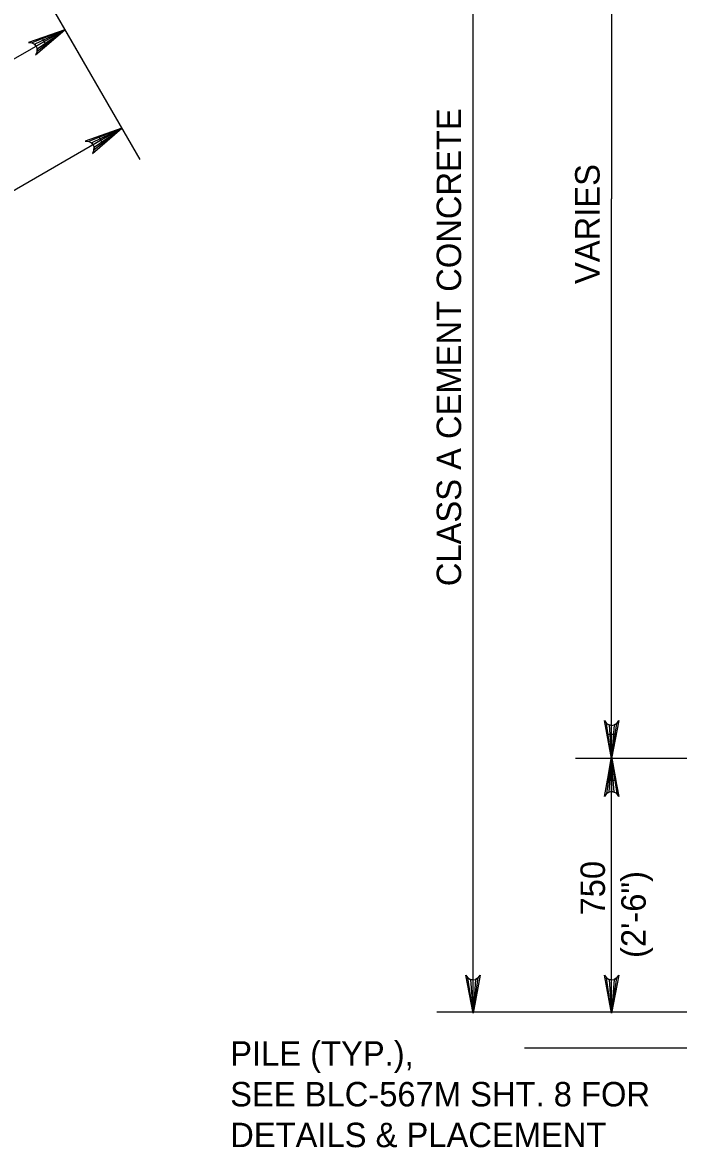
# Model space of a CAD drawing. Extents: x 638340 to 640241, y 295465 to 298435.
# Drawn here: x 638939.7 to 639020.2, y 296989.3 to 297127.3 of the extents above; entities that cross this region are included whole.
import ezdxf

# ---------------------------------------------------------------- set-up
doc = ezdxf.new("R2010")
doc.units = 0
doc.layers.add('3', color=7, linetype='Continuous')

msp = doc.modelspace()

# ---------------------------------------------------------------- linework, layer by layer
at = {"layer": '3'}
for p, q in [((638994.99, 297005.79), (638994.99, 297174.31)), ((639011.99, 297174.31), (639011.99, 297105.67)), ((638919.46, 297170.52), (638947.13, 297122.59)), ((638941.59, 297132.18), (638954.12, 297110.49)), ((638944.92, 297126.42), (638870.33, 297083.36)), ((638951.91, 297114.32), (638874.95, 297069.9)), ((639011.99, 297037.02), (639011.99, 297105.67)), ((639063.19, 297037.02), (639007.56, 297037.02)), ((639011.99, 297005.79), (639011.99, 297037.02)), ((639062.93, 297005.88), (638990.56, 297005.88)), ((639075.05, 297001.5), (639001.3, 297001.5))]:
    msp.add_line(p, q, dxfattribs=at)
for points in [[(638944.92, 297126.42), (638940.45, 297124.85), (638940.88, 297124.81), (638941.2, 297124.63), (638941.4, 297124.39), (638941.51, 297124.09), (638941.51, 297123.73), (638941.32, 297123.33), (638944.92, 297126.42), (638941.51, 297123.73), (638941.51, 297124.09), (638944.92, 297126.42), (638941.4, 297124.39), (638941.2, 297124.63), (638944.92, 297126.42), (638940.88, 297124.81)], [(638951.91, 297114.32), (638947.43, 297112.75), (638947.87, 297112.72), (638948.18, 297112.54), (638948.39, 297112.29), (638948.5, 297111.99), (638948.49, 297111.63), (638948.31, 297111.24), (638951.91, 297114.32), (638948.49, 297111.63), (638948.5, 297111.99), (638951.91, 297114.32), (638948.39, 297112.29), (638948.18, 297112.54), (638951.91, 297114.32), (638947.87, 297112.72)], [(639011.99, 297037.02), (639011.12, 297041.68), (639011.37, 297041.32), (639011.68, 297041.14), (639011.99, 297041.08), (639012.31, 297041.14), (639012.62, 297041.32), (639012.87, 297041.68), (639011.99, 297037.02), (639012.62, 297041.32), (639012.31, 297041.14), (639011.99, 297037.02), (639011.99, 297041.08), (639011.68, 297041.14), (639011.99, 297037.02), (639011.37, 297041.32)], [(639011.99, 297037.02), (639012.87, 297032.36), (639012.62, 297032.72), (639012.31, 297032.9), (639011.99, 297032.96), (639011.68, 297032.9), (639011.37, 297032.72), (639011.12, 297032.36), (639011.99, 297037.02), (639011.37, 297032.72), (639011.68, 297032.9), (639011.99, 297037.02), (639011.99, 297032.96), (639012.31, 297032.9), (639011.99, 297037.02), (639012.62, 297032.72)], [(638994.99, 297005.79), (638994.12, 297010.45), (638994.36, 297010.1), (638994.68, 297009.91), (638994.99, 297009.86), (638995.3, 297009.91), (638995.61, 297010.1), (638995.86, 297010.45), (638994.99, 297005.79), (638995.61, 297010.1), (638995.3, 297009.91), (638994.99, 297005.79), (638994.99, 297009.86), (638994.68, 297009.91), (638994.99, 297005.79), (638994.36, 297010.1)], [(639011.99, 297005.79), (639011.12, 297010.45), (639011.37, 297010.1), (639011.68, 297009.91), (639011.99, 297009.86), (639012.31, 297009.91), (639012.62, 297010.1), (639012.87, 297010.45), (639011.99, 297005.79), (639012.62, 297010.1), (639012.31, 297009.91), (639011.99, 297005.79), (639011.99, 297009.86), (639011.68, 297009.91), (639011.99, 297005.79), (639011.37, 297010.1)]]:
    msp.add_lwpolyline(points, dxfattribs=at)
for points in [[(638942.12, 297125.37), (638942.61, 297124.52), (638944.92, 297126.42)], [(638949.1, 297113.27), (638949.59, 297112.42), (638951.91, 297114.32)], [(639012.49, 297039.97), (639011.5, 297039.97), (639011.99, 297037.02)], [(639012.49, 297034.33), (639011.5, 297034.33), (639011.99, 297037.28)], [(639012.49, 297034.33), (639011.5, 297034.33), (639011.99, 297037.28)]]:
    msp.add_lwpolyline(points, close=True, dxfattribs=at)

# ---------------------------------------------------------------- texts
for s, height, p in [('CLASS A CEMENT CONCRETE', 3.0001, (638993.53, 297058.15)), ('VARIES', 3, (639010.51, 297095.22)), ('750', 3, (639011.17, 297017.76)), ('(2\'-6")', 3, (639016.17, 297012.55))]:
    msp.add_text(s, height=height, rotation=90, dxfattribs=at).set_placement(p)
for s, p in [('PILE (TYP.), ', (638965.2, 296999.34)), ('SEE BLC-567M SHT. 8 FOR', (638965.2, 296994.34)), ('DETAILS & PLACEMENT  ', (638965.2, 296989.34))]:
    msp.add_text(s, height=3.0001, dxfattribs=at).set_placement(p)

doc.saveas('drawing.dxf')
